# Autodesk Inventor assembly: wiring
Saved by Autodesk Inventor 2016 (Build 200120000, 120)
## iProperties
Created: 2018-05
Part Number: wiring
Document SubType Name: Assembly
Designer: Administrator
Title: wiring
Author: Administrator
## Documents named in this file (4)
- c:\worker\convert-fusion-mar-2018\tmp\job-1\16\output\files\8c58ff39-88bb-4352-afd9-60265520bae5\wiring.iam
- c:\worker\convert-fusion-mar-2018\tmp\job-1\16\output\files\8c58ff39-88bb-4352-afd9-60265520bae5\rj45.ipt
- c:\worker\convert-fusion-mar-2018\tmp\job-1\16\output\files\8c58ff39-88bb-4352-afd9-60265520bae5\magnetics.ipt
- c:\worker\convert-fusion-mar-2018\tmp\job-1\16\output\files\8c58ff39-88bb-4352-afd9-60265520bae5\leads.ipt
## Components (3 placed, 3 different names)
1. rj45:1
2. magnetics:1
3. leads:1
